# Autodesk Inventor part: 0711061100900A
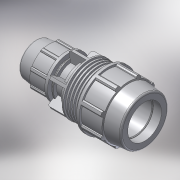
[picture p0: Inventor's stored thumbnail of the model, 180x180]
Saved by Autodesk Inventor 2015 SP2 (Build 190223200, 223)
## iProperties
Created: 2017-02
Part Number: 0711061100900A
Material: PVC-Piping
Description: PLASSON REDUCING COUPLER 110-90
Document SubType Name: Modeling
Designer: KIM
Mass: 92.6774 g
Surface Area: 199.44 cm^2
Volume: 66.1981 cm^3
Density: 1.4 g/cm^3
Appearance: Smooth - White
Author: KIM
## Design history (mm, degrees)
derived "87110.ipt"
feature "Solid1::87110.ipt"
tag "TaggingFeature1"
body "Solid1"
other parameters: "d4" = 31.5, "d5" = 54, "d7" = 181, "d9" = 54, "d11" = 5.4, "d12" = 144.8, "d13" = 120 deg, "d14" = 143, "d15" = 6 deg, "d16" = 162.9, "d18" = 5.5, "d19" = 35 deg, "d20" = 17.5 deg, "d21" = 168.33, "d23" = 0, "d25" = 360 deg, "d27" = 3.62, "d42" = 83.16, "d46" = 2.2, "d51" = 378, "d52" = 54, "d53" = 8 deg, "d54" = 194, "d56" = 126, "d58" = 99, "d59" = 81, "d60" = 138.6, "d61" = 123.2, "d62" = 47.25, "d63" = 68.04, "d64" = 120 deg, "d65" = 154, "d68" = 27, "d74" = 143.22, "d75" = 35 deg, "d76" = 17.5 deg, "d78" = 0, "d80" = 360 deg, "d85" = 3.08, "d88" = 1.8, "d93" = 162, "d94" = 126.7, "d98" = 10.26667, "d99" = 0, "d100" = 7.24, "d102" = 360 deg, "d104" = 2, "d106" = 0, "d107" = 10.26667, "d108" = 0, "d109" = 10.26667, "d110" = 0, "d111" = 3.11667, "d112" = 3.11667, "d113" = 3.11667, "d114" = 3.544, "d116" = 3.544, "d119" = 7.088, "d125" = 159.642, "E_" = 181, "H_" = 378, "l_" = 194, "E_1" = 154, "l_1" = 162, "d96" = 9.35, "d115" = 35.44
